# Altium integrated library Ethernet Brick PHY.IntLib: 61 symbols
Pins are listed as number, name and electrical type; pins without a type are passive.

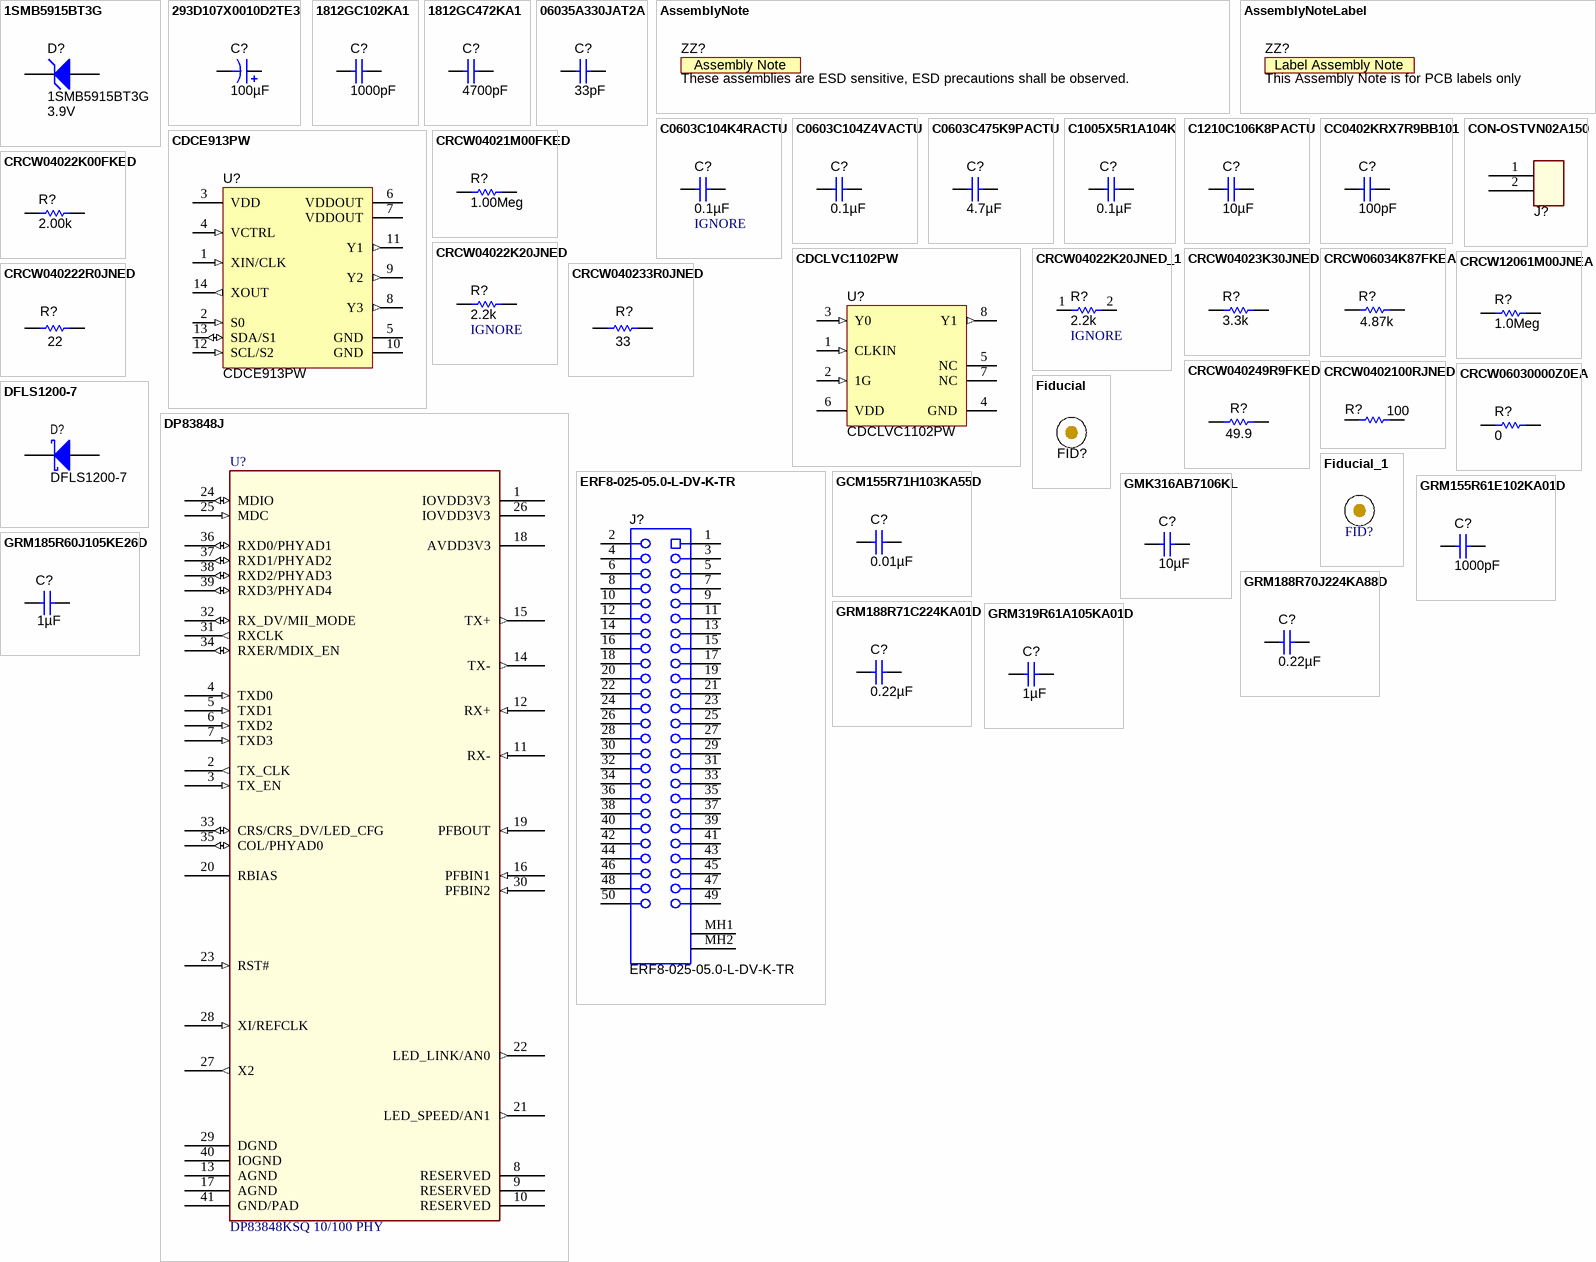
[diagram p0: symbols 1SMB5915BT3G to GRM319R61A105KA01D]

## 1SMB5915BT3G
designator D?  value 3.9V
Diode, Zener, 3.9V, 550mW, SMB; Manufacturer: ON Semiconductor; SymbolCreator: a0412235; U/M: EA; Power_W: 0.55; Vz_V: 3.9; Value1: 0.55W; RJA_CperW: 226
signal-integrity model Diode
footprint SMB
pins: 1 K, 2 A

## 293D107X0010D2TE3
designator C?  ValueDisplayed: 100µF  (hidden comment: 293D107X0010D2TE3)
CAP, TA, 100uF, 10V, +/-20%, 0.6 ohm, SMD; Manufacturer: Vishay-Sprague; Polarized: Y; CompType: Capacitor; U/M: EA; Cap_F: 0.0001; Tolerance_%: 20; Value1: 0.6 ohm; VDC_V: 10; ESR_Ohm: 0.6; IRMS_A: 0.5; TaMin_C: -55; TaMax_C: 125; Cap_Case: D
signal-integrity model Cap
simulation model Cap
footprint 7343-31
pins: 1 +, 2 -

## 1812GC102KA1
designator C?  ValueDisplayed: 1000pF  (hidden comment: 1812GC102KA1)
CAP, CERM, 1000pF, 2000V, +/-10%, X7R, 1812; Manufacturer: AVX; Polarized: N; CompType: Capacitor; U/M: EA; Cap_F: 0.000000001; Tolerance_%: 10; Value1: Unknown; VDC_V: 2000; TaMin_C: -55; TaMax_C: 125; Cap_Case: 1812
signal-integrity model Cap
simulation model Cap
footprint 1812
footprint 1812M
footprint 1812L
footprint 1812_HV
pins: 1, 2

## 1812GC472KA1
designator C?  ValueDisplayed: 4700pF  (hidden comment: 1812GC472KA1)
CAP, CERM, 4700pF, 2000V, +/-10%, X7R, 1812; Manufacturer: AVX; Polarized: N; CompType: Capacitor; U/M: EA; Cap_F: 0.0000000047; Tolerance_%: 10; Value1: Unknown; VDC_V: 2000; TaMin_C: -55; TaMax_C: 125; Cap_Case: 1812
signal-integrity model Cap
simulation model Cap
footprint 1812
footprint 1812M
footprint 1812L
footprint 1812_HV
pins: 1, 2

## 06035A330JAT2A
designator C?  ValueDisplayed: 33pF  (hidden comment: 06035A330JAT2A)
CAP, CERM, 33pF, 50V, +/-5%, C0G/NP0, 0603; Manufacturer: AVX; Polarized: N; CompType: Capacitor; U/M: EA; Cap_F: 0.000000000033; Tolerance_%: 5; ESR_Ohm: 0.209; Value1: 0.209 ohm; VDC_V: 50; TaMin_C: -55; TaMax_C: 125; Cap_Case: 0603
signal-integrity model Cap
simulation model Cap
footprint 0603
footprint 0603M
footprint 0603L
footprint 0603_HV
pins: 1, 2

## AssemblyNote
designator ZZ?, comment These assemblies are ESD sensitive, ESD precautions shall be observed.  (no BOM)
SymbolCreator: codlsc; CompType: AssemblyNote
footprint AssemblyNote

## AssemblyNoteLabel
designator ZZ?, comment This Assembly Note is for PCB labels only  (no BOM)
SymbolCreator: a0412235
footprint AssemblyNoteLabel

## C0603C104K4RACTU
designator C?  ValueDisplayed: 0.1µF  (hidden comment: C0603C104K4RACTU)
CAP, CERM, 0.1uF, 16V, +/-10%, X7R, 0603; Manufacturer: Kemet; Polarized: N; CompType: Capacitor; U/M: EA; Cap_F: 0.0000001; Tolerance_%: 10; Value1: Unknown; VDC_V: 16; TaMin_C: -55; TaMax_C: 125; Cap_Case: 0603
signal-integrity model Cap
simulation model Cap
footprint 0603
footprint 0603M
footprint 0603L
footprint 0603_HV
pins: 1, 2

## C0603C104Z4VACTU
designator C?  ValueDisplayed: 0.1µF  (hidden comment: C0603C104Z4VACTU)
CAP, CERM, 0.1uF, 16V, +80/-20%, Y5V, 0603; Manufacturer: Kemet; Polarized: N; CompType: Capacitor; U/M: EA; Cap_F: 0.0000001; Tolerance_%: 80; Value1: Unknown; VDC_V: 16; TaMin_C: -30; TaMax_C: 85; Cap_Case: 0603
signal-integrity model Cap
simulation model Cap
footprint 0603
footprint 0603M
footprint 0603L
footprint 0603_HV
pins: 1, 2

## C0603C475K9PACTU
designator C?  ValueDisplayed: 4.7µF  (hidden comment: C0603C475K9PACTU)
CAP, CERM, 4.7uF, 6.3V, +/-10%, X5R, 0603; Manufacturer: Kemet; Polarized: N; CompType: Capacitor; U/M: EA; Cap_F: 0.0000047; Tolerance_%: 10; ESR_Ohm: 0.006; Value1: 0.006 ohm; VDC_V: 6.3; IRMS_A: 7.24; TaMin_C: -55; TaMax_C: 85; Cap_Case: 0603
signal-integrity model Cap
simulation model Cap
footprint 0603
footprint 0603M
footprint 0603L
footprint 0603_HV
pins: 1, 2

## C1005X5R1A104K
designator C?  ValueDisplayed: 0.1µF  (hidden comment: C1005X5R1A104K)
CAP, CERM, 0.1uF, 10V, +/-10%, X5R, 0402; Manufacturer: TDK; Polarized: N; CompType: Capacitor; U/M: EA; Cap_F: 0.0000001; Tolerance_%: 10; ESR_Ohm: 0.0186; Value1: 0.0186 ohm; TaMin_C: -55; TaMax_C: 85; Cap_Case: 0402
signal-integrity model Cap
simulation model Cap
footprint 0402
footprint 0402M
footprint 0402L
footprint 0402S
pins: 1, 2

## C1210C106K8PACTU
designator C?  ValueDisplayed: 10µF  (hidden comment: C1210C106K8PACTU)
CAP, CERM, 10uF, 10V, +/-10%, X5R, 1210; Manufacturer: Kemet; Polarized: N; CompType: Capacitor; U/M: EA; Cap_F: 0.00001; Tolerance_%: 10; ESR_Ohm: 0.008; Value1: 0.008 ohm; IRMS_A: 6.9; TaMin_C: -55; TaMax_C: 85; Cap_Case: 1210
signal-integrity model Cap
simulation model Cap
footprint 1210
footprint 1210M
footprint 1210L
pins: 1, 2

## CC0402KRX7R9BB101
designator C?  ValueDisplayed: 100pF  (hidden comment: CC0402KRX7R9BB101)
CAP, CERM, 100pF, 50V, +/-10%, X7R, 0402; Manufacturer: Yageo America; Polarized: N; CompType: Capacitor; U/M: EA; Cap_F: 0.0000000001; Tolerance_%: 10; Value1: Unknown; VDC_V: 50; TaMin_C: -55; TaMax_C: 125; Cap_Case: 0402
signal-integrity model Cap
simulation model Cap
footprint 0402
footprint 0402M
footprint 0402L
footprint 0402S
pins: 1, 2

## CDCE913PW
designator U?
Programmable 1-PLL VCXO Clock Synthesizer With 1.8-V, 2.5-V, and 3.3-V Outputs, PW0014A; Alternate Manufacturer: None; Manufacturer: Texas Instruments; SymbolCreator: a0411947; CompType: IC; U/M: EA
footprint PW0014A_N
footprint PW0014A_M
footprint PW0014A_L
pins: 1 XIN/CLK (in), 2 S0 (in), 3 VDD (power), 4 VCTRL (in), 5 GND (power), 6 VDDOUT (power), 7 VDDOUT (power), 8 Y3 (out), 9 Y2 (out), 10 GND (power), 11 Y1 (out), 12 SCL/S2 (in), 13 SDA/S1 (io), 14 XOUT (out)

## CDCLVC1102PW
designator U?
3.3 V and 2.5 V LVCMOS High-Performance Clock Buffer Family, PW0008A; Alternate Manufacturer: None; Manufacturer: Texas Instruments; SymbolCreator: a0799628; CompType: IC; U/M: EA
footprint PW0008A_N
footprint PW0008A_M
footprint PW0008A_L
pins: 1 CLKIN (in), 2 1G (in), 3 Y0 (in), 4 GND (power), 5 NC, 6 VDD (power), 7 NC, 8 Y1 (out)

## CON-OSTVN02A150
designator J?  (value not drawn)
CONN TERM BLOCK 2.54MM 2POS PCB; Manufacturer: On Shore Technology Inc; SymbolCreator: x0120606; CompType: Terminal Block
footprint CN2_MTB_P100_PD80_D1.1_S5.54X6.5_STACK
pins: 1, 2

## CRCW04021M00FKED
designator R?  value 1.00Meg  (hidden comment: CRCW04021M00FKED)
RES, 1.00Meg ohm, 1%, 0.063W, 0402; Manufacturer: Vishay-Dale; CompType: Resistor; Res_ohm: 1000000; Value_Code: 1M00; Tolerance_%: 1; Power_W: 0.063; VDC_V: 50; TempCo: 100 ppm/C; EIA_Code: E96; U/M: EA
signal-integrity model Resistor
simulation model Resistor
footprint 0402
footprint 0402M
footprint 0402L
footprint 0402S
pins: 1, 2

## CRCW04022K00FKED
designator R?  value 2.00k  (hidden comment: CRCW04022K00FKED)
RES, 2.00k ohm, 1%, 0.063W, 0402; Manufacturer: Vishay-Dale; CompType: Resistor; Res_ohm: 2000; Value_Code: 2k00; Tolerance_%: 1; Power_W: 0.063; VDC_V: 50; TempCo: 100 ppm/C; EIA_Code: E96; U/M: EA
signal-integrity model Resistor
simulation model Resistor
footprint 0402
footprint 0402M
footprint 0402L
footprint 0402S
pins: 1, 2

## CRCW04022K20JNED
designator R?  value 2.2k  (hidden comment: CRCW04022K20JNED)
RES, 2.2k ohm, 5%, 0.063W, 0402; Manufacturer: Vishay-Dale; CompType: Resistor; Res_ohm: 2200; Value_Code: 2k20; Tolerance_%: 5; Power_W: 0.063; VDC_V: 50; TempCo: 200 ppm/C; EIA_Code: E24; U/M: EA
signal-integrity model Resistor
simulation model Resistor
footprint 0402
footprint 0402M
footprint 0402L
footprint 0402S
pins: 1, 2

## CRCW04022K20JNED_1
designator R?, comment value 2.2k  (hidden comment: CRCW04022K20JNED)
RES, 2.2k ohm, 5%, 0.063W, 0402; Manufacturer: Vishay-Dale; CompType: Resistor; Res_ohm: 2200; Value_Code: 2k20; Tolerance_%: 5; Power_W: 0.063; VDC_V: 50; TempCo: 200 ppm/C; EIA_Code: E24; U/M: EA
signal-integrity model Resistor
simulation model Resistor
footprint 0402
footprint 0402M
footprint 0402L
footprint 0402S
pins: 1, 2

## CRCW04023K30JNED
designator R?  value 3.3k  (hidden comment: CRCW04023K30JNED)
RES, 3.3k ohm, 5%, 0.063W, 0402; Manufacturer: Vishay-Dale; CompType: Resistor; Res_ohm: 3300; Value_Code: 3k30; Tolerance_%: 5; Power_W: 0.063; VDC_V: 50; TempCo: 200 ppm/C; EIA_Code: E24; U/M: EA
signal-integrity model Resistor
simulation model Resistor
footprint 0402
footprint 0402M
footprint 0402L
footprint 0402S
pins: 1, 2

## CRCW06034K87FKEA
designator R?  value 4.87k  (hidden comment: CRCW06034K87FKEA)
RES, 4.87k ohm, 1%, 0.1W, 0603; Manufacturer: Vishay-Dale; CompType: Resistor; Res_ohm: 4870; Value_Code: 4k87; Tolerance_%: 1; Power_W: 0.1; VDC_V: 75; TempCo: 100 ppm/C; EIA_Code: E96; U/M: EA
signal-integrity model Resistor
simulation model Resistor
footprint 0603
footprint 0603M
footprint 0603L
footprint 0603_HV
pins: 1, 2

## CRCW12061M00JNEA
designator R?  value 1.0Meg  (hidden comment: CRCW12061M00JNEA)
RES, 1.0Meg ohm, 5%, 0.25W, 1206; Manufacturer: Vishay-Dale; CompType: Resistor; Res_ohm: 1000000; Value_Code: 1M00; Tolerance_%: 5; Power_W: 0.25; VDC_V: 200; TempCo: 200 ppm/C; EIA_Code: E24; U/M: EA
signal-integrity model Resistor
simulation model Resistor
footprint 1206
footprint 1206M
footprint 1206L
pins: 1, 2

## CRCW040222R0JNED
designator R?  value 22  (hidden comment: CRCW040222R0JNED)
RES, 22 ohm, 5%, 0.063W, 0402; Manufacturer: Vishay-Dale; CompType: Resistor; Value_Code: 22R0; Tolerance_%: 5; Power_W: 0.063; VDC_V: 50; TempCo: 200 ppm/C; EIA_Code: E24; U/M: EA
signal-integrity model Resistor
simulation model Resistor
footprint 0402
footprint 0402M
footprint 0402L
footprint 0402S
pins: 1, 2

## CRCW040233R0JNED
designator R?  value 33  (hidden comment: CRCW040233R0JNED)
RES, 33 ohm, 5%, 0.063W, 0402; Manufacturer: Vishay-Dale; CompType: Resistor; Value_Code: 33R0; Tolerance_%: 5; Power_W: 0.063; VDC_V: 50; TempCo: 200 ppm/C; EIA_Code: E24; U/M: EA
signal-integrity model Resistor
simulation model Resistor
footprint 0402
footprint 0402M
footprint 0402L
footprint 0402S
pins: 1, 2

## CRCW040249R9FKED
designator R?  value 49.9  (hidden comment: CRCW040249R9FKED)
RES, 49.9 ohm, 1%, 0.063W, 0402; Manufacturer: Vishay-Dale; CompType: Resistor; Value_Code: 49R9; Tolerance_%: 1; Power_W: 0.063; VDC_V: 50; TempCo: 100 ppm/C; EIA_Code: E96; U/M: EA
signal-integrity model Resistor
simulation model Resistor
footprint 0402
footprint 0402M
footprint 0402L
footprint 0402S
pins: 1, 2

## CRCW0402100RJNED
designator R?  value 100  (hidden comment: CRCW0402100RJNED)
RES, 100 ohm, 5%, 0.063W, 0402; Manufacturer: Vishay-Dale; CompType: Resistor; Value_Code: 100R; Tolerance_%: 5; Power_W: 0.063; VDC_V: 50; TempCo: 200 ppm/C; EIA_Code: E24; U/M: EA
signal-integrity model Resistor
simulation model Resistor
footprint 0402
footprint 0402M
footprint 0402L
footprint 0402S
pins: 1, 2

## CRCW06030000Z0EA
designator R?  value 0  (hidden comment: CRCW06030000Z0EA)
RES, 0 ohm, 5%, 0.1W, 0603; Manufacturer: Vishay-Dale; CompType: Resistor; Value_Code: 0000; Tolerance_%: 5; Power_W: 0.1; VDC_V: 75; TempCo: 200 ppm/C; EIA_Code: E24; U/M: EA
signal-integrity model Resistor
simulation model Resistor
footprint 0603
footprint 0603M
footprint 0603L
footprint 0603_HV
pins: 1, 2

## DFLS1200-7
designator D?
Diode, Schottky, 200V, 1A, PowerDI123; Manufacturer: Diodes Inc.; U/M: EA; Vf_V: 0.85; Value2: 0.85V; Io_A: 1; Vr_V: 200; TJmax_C: 175; RJC_CperW: 7
signal-integrity model Diode
simulation model DI_DFLS1200
footprint powerDI123
pins: 1 K, 2 A

## DP83848J
designator U?, comment DP83848KSQ 10/100 PHY
TI DP83848J 10/100 PHY; Manufacturer: Texas Instruments; Manufacturer PN: DP83848KSQ/NOPB
footprint QFN50P600X600X80-40N (QFN, 40-Leads, Body 6.1x6.1mm (max), Pitch 0.50mm, IPC Medium Density)
footprint QFN50P600X600X80-40N (QFN, 40-Leads, Body 6.1x6.1mm (max), Pitch 0.50mm, IPC Medium Density)
pins: 1 IOVDD3V3 (power), 2 TX_CLK (out), 3 TX_EN (in), 4 TXD0 (in), 5 TXD1 (in), 6 TXD2 (in), 7 TXD3 (in), 8 RESERVED, 9 RESERVED, 10 RESERVED, 11 RX- (in), 12 RX+ (in), 13 AGND (power), 14 TX- (out), 15 TX+ (out), 16 PFBIN1 (in), 17 AGND (power), 18 AVDD3V3 (power), 19 PFBOUT (in), 20 RBIAS (power), 21 LED_SPEED/AN1 (out), 22 LED_LINK/AN0 (out), 23 RST# (in), 24 MDIO (io), 25 MDC (in), 26 IOVDD3V3 (power), 27 X2 (out), 28 XI/REFCLK (in), 29 DGND (power), 30 PFBIN2 (in), 31 RXCLK (out), 32 RX_DV/MII_MODE (io), 33 CRS/CRS_DV/LED_CFG (io), 34 RXER/MDIX_EN (io), 35 COL/PHYAD0 (io), 36 RXD0/PHYAD1 (io), 37 RXD1/PHYAD2 (io), 38 RXD2/PHYAD3 (io), 39 RXD3/PHYAD4 (io), 40 IOGND (power), 41 GND/PAD (power)

## ERF8-025-05.0-L-DV-K-TR
designator J?
Receptacle, 0.8mm, 25x2, SMT; Manufacturer: Samtec; SymbolCreator: a0412235; CompType: Connector; U/M: EA
footprint CONN_ERF8-025-05_0-L-DV-L-TR
pins: 1, 2, 3, 4, 5, 6, 7, 8, 9, 10, 11, 12, 13, 14, 15, 16, 17, 18, 19, 20, 21, 22, 23, 24, 25, 26, 27, 28, 29, 30, 31, 32, 33, 34, 35, 36, 37, 38, 39, 40, 41, 42, 43, 44, 45, 46, 47, 48, 49, 50, MH1 51, MH2 52

## Fiducial
designator FID?  (value not drawn)
Fiducial mark.  There is nothing to buy or mount.; SymbolCreator: codlsc
footprint Fiducial10-30
footprint Fiducial10-20
footprint Fiducial15-30
footprint Fiducial20-40
footprint Fiducial6.4-20
footprint Fiducial10-30_TopLayerKeepOutOnly
footprint Fiducial6.4-20_TopLayerKeepOutOnly
footprint Fiducial10-20_TopLayerKeepOutOnly
footprint Fiducial15-30_TopLayerKeepOutOnly
footprint Fiducial20-40_TopLayerKeepOutOnly

## Fiducial_1
designator FID?, comment Fiducial  (value not drawn)
Fiducial mark.  There is nothing to buy or mount.; SymbolCreator: codlsc
footprint Fiducial10-30
footprint Fiducial10-20
footprint Fiducial15-30
footprint Fiducial20-40
footprint Fiducial6.4-20
footprint Fiducial10-30_Panel

## GCM155R71H103KA55D
designator C?  ValueDisplayed: 0.01µF  (hidden comment: GCM155R71H103KA55D)
CAP, CERM, 0.01uF, 50V, +/-10%, C0G/NP0, 0402; Manufacturer: MuRata; Polarized: N; CompType: Capacitor; U/M: EA; Cap_F: 0.00000001; Tolerance_%: 10; Value1: Unknown; VDC_V: 50; TaMin_C: -55; TaMax_C: 125; Cap_Case: 0402
signal-integrity model Cap
simulation model Cap
footprint 0402
footprint 0402M
footprint 0402L
footprint 0402S
pins: 1, 2

## GMK316AB7106KL
designator C?  ValueDisplayed: 10µF  (hidden comment: GMK316AB7106KL)
CAP, CERM, 10uF, 35V, +/-10%, X7R, 1206; Manufacturer: Taiyo Yuden; Polarized: N; CompType: Capacitor; U/M: EA; Cap_F: 0.00001; Tolerance_%: 10; Value1: Unknown; VDC_V: 35; TaMin_C: -55; TaMax_C: 125; Cap_Case: 1206
signal-integrity model Cap
simulation model Cap
footprint 1206
footprint 1206M
footprint 1206L
pins: 1, 2

## GRM155R61E102KA01D
designator C?  ValueDisplayed: 1000pF  (hidden comment: GRM155R61E102KA01D)
CAP, CERM, 1000pF, 25V, +/-10%, X5R, 0402; Manufacturer: MuRata; Polarized: N; CompType: Capacitor; U/M: EA; Cap_F: 0.000000001; Tolerance_%: 10; Value1: Unknown; VDC_V: 25; TaMin_C: -55; TaMax_C: 85; Cap_Case: 0402
signal-integrity model Cap
simulation model Cap
footprint 0402
footprint 0402M
footprint 0402L
footprint 0402S
pins: 1, 2

## GRM185R60J105KE26D
designator C?  ValueDisplayed: 1µF  (hidden comment: GRM185R60J105KE26D)
CAP, CERM, 1uF, 6.3V, +/-10%, X5R, 0603; Manufacturer: MuRata; Polarized: N; CompType: Capacitor; U/M: EA; Cap_F: 0.000001; Tolerance_%: 10; Value1: Unknown; VDC_V: 6.3; TaMin_C: -55; TaMax_C: 85; Cap_Case: 0603
signal-integrity model Cap
simulation model Cap
footprint 0603
footprint 0603M
footprint 0603L
footprint 0603_HV
pins: 1, 2

## GRM188R70J224KA88D
designator C?  ValueDisplayed: 0.22µF  (hidden comment: GRM188R70J224KA88D)
CAP, CERM, 0.22uF, 6.3V, +/-10%, X7R, 0603; Manufacturer: MuRata; Polarized: N; CompType: Capacitor; U/M: EA; Cap_F: 0.00000022; Tolerance_%: 10; Value1: Unknown; VDC_V: 6.3; TaMin_C: -55; TaMax_C: 125; Cap_Case: 0603
signal-integrity model Cap
simulation model Cap
footprint 0603
footprint 0603M
footprint 0603L
footprint 0603_HV
pins: 1, 2

## GRM188R71C224KA01D
designator C?  ValueDisplayed: 0.22µF  (hidden comment: GRM188R71C224KA01D)
CAP, CERM, 0.22uF, 16V, +/-10%, X7R, 0603; Manufacturer: MuRata; Polarized: N; CompType: Capacitor; U/M: EA; Cap_F: 0.00000022; Tolerance_%: 10; Value1: Unknown; VDC_V: 16; TaMin_C: -55; TaMax_C: 125; Cap_Case: 0603
signal-integrity model Cap
simulation model Cap
footprint 0603
footprint 0603M
footprint 0603L
footprint 0603_HV
pins: 1, 2

## GRM319R61A105KA01D
designator C?  ValueDisplayed: 1µF  (hidden comment: GRM319R61A105KA01D)
CAP, CERM, 1uF, 10V, +/-10%, X5R, 1206; Manufacturer: MuRata; Polarized: N; CompType: Capacitor; U/M: EA; Cap_F: 0.000001; Tolerance_%: 10; Value1: Unknown; TaMin_C: -55; TaMax_C: 85; Cap_Case: 1206
signal-integrity model Cap
simulation model Cap
footprint 1206
footprint 1206M
footprint 1206L
pins: 1, 2

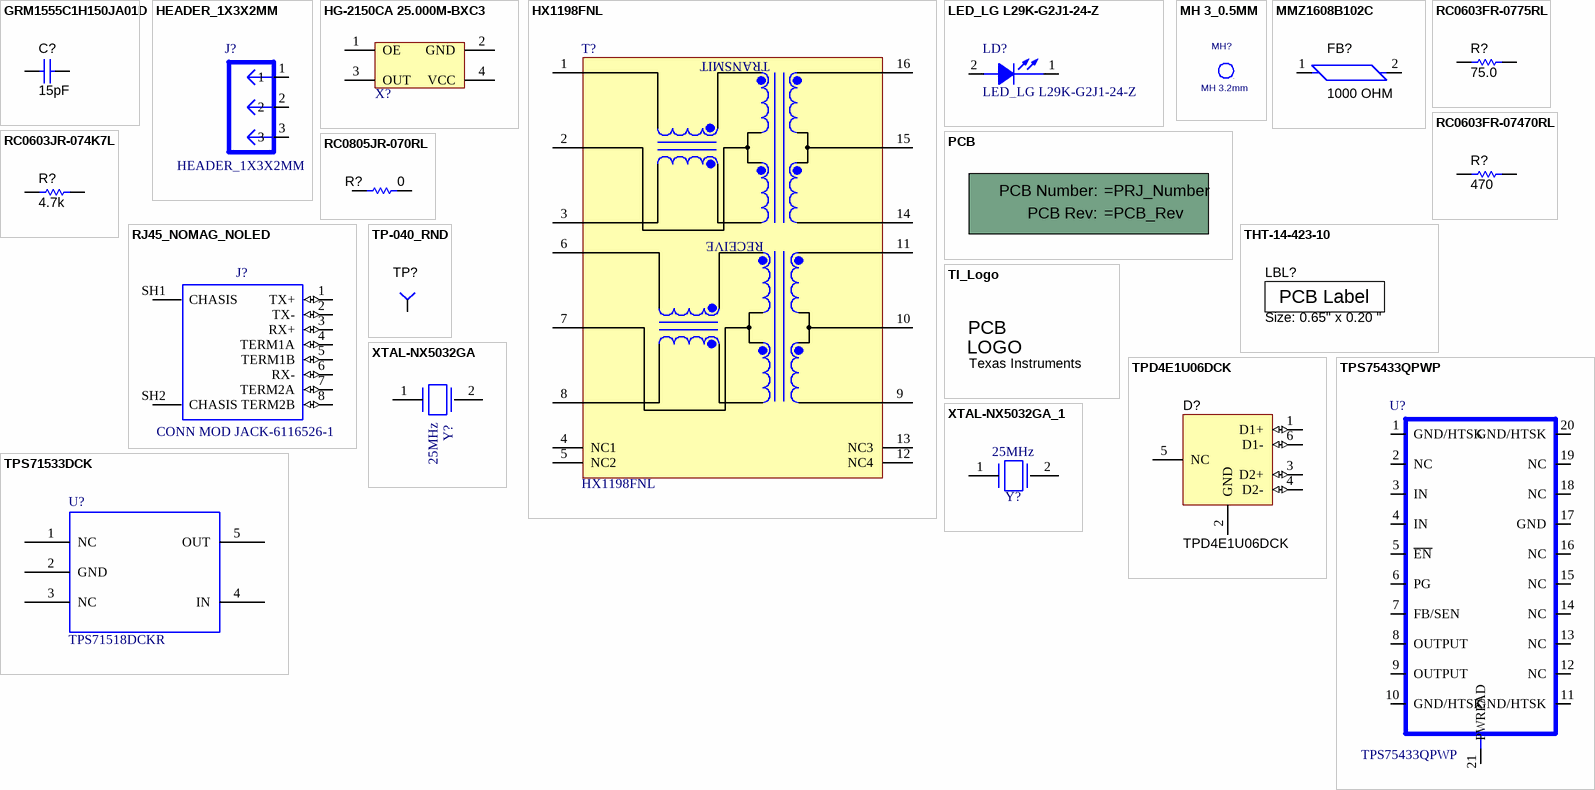
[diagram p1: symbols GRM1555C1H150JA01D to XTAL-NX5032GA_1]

## GRM1555C1H150JA01D
designator C?  ValueDisplayed: 15pF  (hidden comment: GRM1555C1H150JA01D)
CAP, CERM, 15pF, 50V, +/-5%, C0G/NP0, 0402; Manufacturer: MuRata; Polarized: N; CompType: Capacitor; U/M: EA; Cap_F: 0.000000000015; Tolerance_%: 5; Value1: Unknown; VDC_V: 50; TaMin_C: -55; TaMax_C: 125; Cap_Case: 0402
signal-integrity model Cap
simulation model Cap
footprint 0402
footprint 0402M
footprint 0402L
footprint 0402S
pins: 1, 2

## HEADER_1X3X2MM
designator J?
CONN HEADER 3POS 2MM VERT T/H; Manufacturer: 3M; PartNumber: 951103-8622-AR; area: 19600; Value: 951103-8622-AR
footprint HEADER_1X3X2MM
pins: 1, 2, 3

## HG-2150CA 25.000M-BXC3
designator X?  (value not drawn)
OSC 25.00 MHZ 3.3V HIGH STAB SMD; Manufacturer: EPSON; Value: 25MHz
footprint OSC_HG-2150CA
pins: 1 OE, 2 GND, 3 OUT, 4 VCC

## HX1198FNL
designator T?
TRANSFORMER, MDL, XFMR SGL ETHR LAN, SOIC-16; Manufacturer: PULSE ELECTRONICS; SymbolCreator: x0199378
footprint XFMR_ HX1198FNL (TRANSFORMER, MODULE XFMR, 16-SOIC)
pins: 1 TD+, 2 TCT, 3 TD-, 4 NC1, 5 NC2, 6 RD+, 7 RCT, 8 RD-, 9 RX-, 10 CMT, 11 RX+, 12 NC4, 13 NC3, 14 TX-, 15 CMT, 16 TX+

## LED_LG L29K-G2J1-24-Z
designator LD?
LED SmartLED Green 570NM; Manufacturer: OSRAM; SymbolCreator: x0120606
footprint LED0603AA
pins: 1 C, 2 A

## MH 3_0.5MM
designator MH?, comment MH 3.2mm
Mountin hole, NPTH Drill 3.2mm
footprint MH3.2_H5_W6_KO8_STARHEAD
pins: 1

## MMZ1608B102C
designator FB?, comment 1000 OHM
FERRITE CHIP 1000 OHM 300MA 0603; PartNumber: MMZ1608B102C; Manufacturer: TDK Corporation; CompType: Ferrite Bead
footprint FB0603
pins: 1, 2

## PCB
designator !PCB?, comment Printed Circuit Board  (value not drawn)  (mechanical)
Manufacturer: Any; SymbolCreator: a0412235; CompType: PCB
1 alternate drawing of the same symbol

## RC0603FR-0775RL
designator R?  value 75.0  (hidden comment: RC0603FR-0775RL)
RES, 75.0 ohm, 1%, 0.1W, 0603; Manufacturer: Yageo America; CompType: Resistor; Res_ohm: 75; Value_Code: 75R0; Tolerance_%: 1; Power_W: 0.1; VDC_V: 150; TempCo: 200 ppm/C; EIA_Code: E96; U/M: EA
signal-integrity model Resistor
simulation model Resistor
footprint 0603
footprint 0603M
footprint 0603L
footprint 0603_HV
pins: 1, 2

## RC0603FR-07470RL
designator R?  value 470  (hidden comment: RC0603FR-07470RL)
RES, 470 ohm, 1%, 0.1W, 0603; Manufacturer: Yageo America; CompType: Resistor; Value_Code: 470R; Tolerance_%: 1; Power_W: 0.1; VDC_V: 150; TempCo: 200 ppm/C; U/M: EA
signal-integrity model Resistor
simulation model Resistor
footprint 0603
footprint 0603M
footprint 0603L
footprint 0603_HV
pins: 1, 2

## RC0603JR-074K7L
designator R?  value 4.7k  (hidden comment: RC0603JR-074K7L)
RES, 4.7k ohm, 5%, 0.1W, 0603; Manufacturer: Yageo America; CompType: Resistor; Res_ohm: 4700; Value_Code: 4k70; Tolerance_%: 5; Power_W: 0.1; VDC_V: 50; TempCo: 100 ppm/C; EIA_Code: E24; U/M: EA
signal-integrity model Resistor
simulation model Resistor
footprint 0603
footprint 0603M
footprint 0603L
footprint 0603_HV
pins: 1, 2

## RC0805JR-070RL
designator R?  value 0  (hidden comment: RC0805JR-070RL)
RES, 0 ohm, 5%, 0.125W, 0805; Manufacturer: Yageo America; CompType: Resistor; Value_Code: 0000; Tolerance_%: 5; Power_W: 0.125; VDC_V: 150; TempCo: 200 ppm/C; EIA_Code: E24; U/M: EA
signal-integrity model Resistor
simulation model Resistor
footprint 0805_HV
footprint 0805
footprint 0805M
footprint 0805L
pins: 1, 2

## RJ45_NOMAG_NOLED
designator J?, comment CONN MOD JACK-6116526-1
CONN MOD JACK R/A 8P8C SHIELDED; Manufacturer: TE Connectivity; PCB DECAL: 406541; GNUM: G20-8RJ45-ENET-AAA
footprint TE_6116526-1
pins: 1 TX+ (io), 2 TX- (io), 3 RX+ (io), 4 TERM1A (io), 5 TERM1B (io), 6 RX- (io), 7 TERM2A (io), 8 TERM2B (io), SH1 CHASIS, SH2 CHASIS

## THT-14-423-10
designator LBL?, comment Size: 0.65" x 0.20 "
Thermal Transfer Printable Labels, 0.650" W x 0.200" H - 10,000 per roll; Manufacturer: Brady; PartNumber: THT-14-423-10; SymbolCreator: a0412235; CompType: Label
footprint Label_650x200

## TI_Logo
designator Logo?, comment Texas Instruments  (no BOM)
Texas Instrument Corporate Signature; SymbolCreator: codlsc
footprint TI_Stacked_SolderMask_Medium
footprint TI_Stacked_SolderMask_Small
footprint TI_Stacked_Overlay_Medium
footprint TI_Stacked_Overlay_Small
footprint TI_Horizontal_SolderMask_Medium
footprint TI_Horizontal_SolderMask_Small
footprint TI_Horizontal_Overlay_Medium
footprint TI_Horizontal_Overlay_Small
footprint TI_Symbol_SolderMask_Small
footprint TI_Symbol_Overlay_Medium
footprint TI_Symbol_Overlay_Small
footprint TI_Symbol_SolderMask_Medium

## TP-040_RND
designator TP?  (value not drawn)
Test Point 40mil pad 20mil drill; Manufacturer: STD; Description: Test Point, O.040 Hole; Value: STD
footprint TP-040_RND
footprint TP1_PD40_D0.5_S50
pins: 1

## TPD4E1U06DCK
designator D?
Quad Channel High Speed ESD Protection Device, DCK0006A; Alternate Manufacturer: None; Manufacturer: Texas Instruments; SymbolCreator: a0411947; CompType: IC; U/M: EA
footprint DCK0006A_N
footprint DCK0006A_M
footprint DCK0006A_L
pins: 1 D1+ (io), 2 GND (power), 3 D2+ (io), 4 D2- (io), 5 NC, 6 D1- (io)

## TPS71533DCK
designator U?, comment TPS71518DCKR
IC REG LDO 1.8V 50MA SC70-5; Manufacturer: TI; Alternate Manufacturer: None; Area: 30405
footprint SOP_5P.65MM(DCK)
pins: 1 NC, 2 GND, 3 NC, 4 IN, 5 OUT

## TPS75433QPWP
designator U?
IC, Low Dropout Voltage Regulator, 3.3 V, 2.0 A; Manufacturer: Texas Instruments; Alternate Manufacturer: None; Area: 96000
footprint PWP20
pins: 1 GND/HTSK, 2 NC, 3 IN, 4 IN, 5 ~{EN}, 6 PG, 7 FB/SEN, 8 OUTPUT, 9 OUTPUT, 10 GND/HTSK, 11 GND/HTSK, 12 NC, 13 NC, 14 NC, 15 NC, 16 NC, 17 GND, 18 NC, 19 NC, 20 GND/HTSK, 21 PWRPAD

## XTAL-NX5032GA
designator Y?, comment value 25MHz  (hidden comment: XTAL-445I23D25M00000)
CRYSTAL 25.0MHZ 18PF SMD; Manufacturer: CTS-Frequency Controls
footprint XTAL_ATS250BSM-1E_1 (CRYSTAL, SMD-2P)
pins: 1, 2

## XTAL-NX5032GA_1
designator Y?, comment value 25MHz  (hidden comment: XTAL-ATS250BSM-1E)
CRYSTAL 25.0MHZ 18PF SMD; Manufacturer: CTS-Frequency Controls; PartNumber: 445I23D25M00000
footprint XTAL_ATS250BSM-1E_1 (CRYSTAL, SMD-2P)
pins: 1, 2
